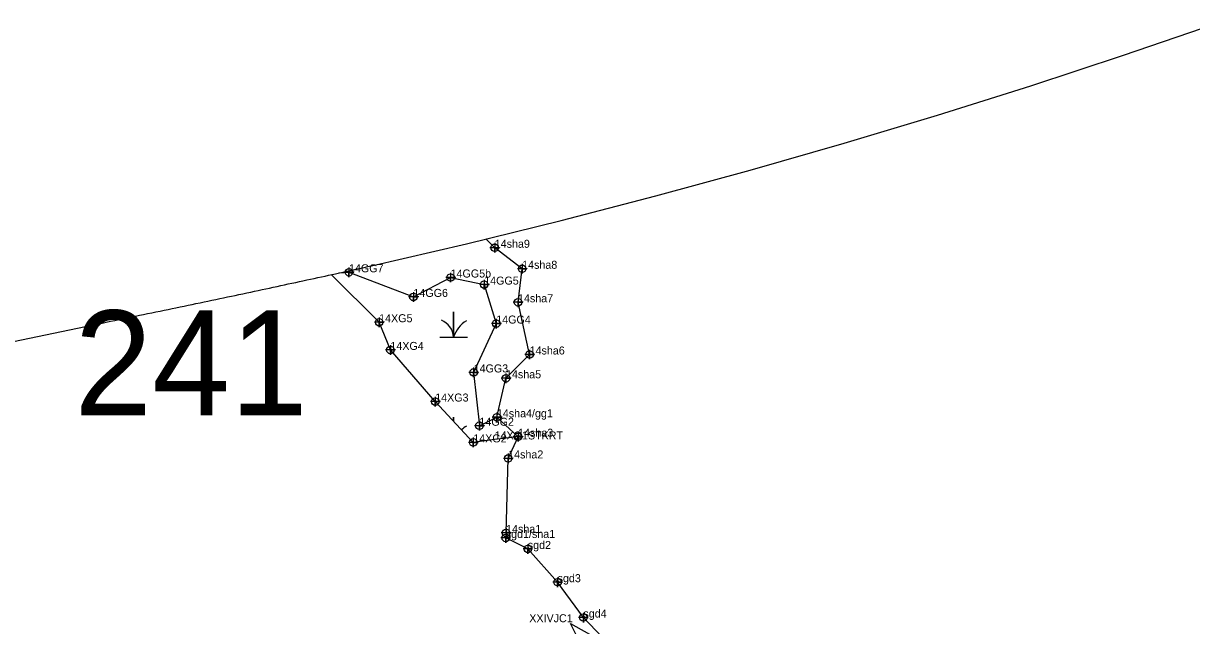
# Model space of a CAD drawing. Extents: x 2071991 to 2268989, y 436479 to 469629.
# Drawn here: x 2262836 to 2263565, y 442642 to 443018 of the extents above; entities that cross this region are included whole.
import ezdxf

# ---------------------------------------------------------------- set-up
doc = ezdxf.new("R2010")
doc.units = 0
for name, color, linetype in [('approx_PSA', 7, 'Continuous'), ('Default', 7, 'Continuous'), ('Exist Environmental Wetland Boundary', 7, 'Continuous'), ('Exist Environmental Wetland Boundary Cogo Comment', 7, 'Continuous'), ('Exist Environmental Wetland Boundary Cogo Point CELL', 7, 'Continuous'), ('Exist Hydro Jurisdictional Stream or Body of Water NEU Mitigable', 7, 'Continuous'), ('Exist Hydro Jurisdictional Stream or Body of Water NEU Mitigable Cogo Comment', 7, 'Continuous'), ('Exist Hydro Jurisdictional Stream or Body of Water NEU Mitigable Cogo Point CELL', 7, 'Continuous'), ('Exist Hydro Swamp or Marsh', 7, 'Continuous')]:
    doc.layers.add(name, color=color, linetype=linetype)

msp = doc.modelspace()

# ---------------------------------------------------------------- linework, layer by layer
at = {"layer": 'approx_PSA'}
for p, q in [((2263522.98, 442997.73), (2263580.7, 443017.56)), ((2263465, 442978.66), (2263522.98, 442997.73)), ((2263406.78, 442960.33), (2263465, 442978.66)), ((2263348.33, 442942.76), (2263406.78, 442960.33)), ((2263289.66, 442925.94), (2263348.33, 442942.76)), ((2263230.78, 442909.88), (2263289.66, 442925.94)), ((2263171.7, 442894.58), (2263230.78, 442909.88)), ((2263112.42, 442880.04), (2263171.7, 442894.58)), ((2263053.23, 442866.33), (2263112.42, 442880.04)), ((2263030.75, 442861.33), (2263033.17, 442861.87)), ((2263033.17, 442861.87), (2263035.46, 442862.37)), ((2263035.46, 442862.37), (2263037.57, 442862.84)), ((2263037.57, 442862.84), (2263039.82, 442863.33)), ((2263039.82, 442863.33), (2263041.89, 442863.79)), ((2263041.89, 442863.79), (2263044.17, 442864.3)), ((2263044.17, 442864.3), (2263046.46, 442864.81)), ((2263046.46, 442864.81), (2263048.53, 442865.28)), ((2263048.53, 442865.28), (2263050.77, 442865.78)), ((2263050.77, 442865.78), (2263052.96, 442866.27)), ((2263052.96, 442866.27), (2263053.23, 442866.33)), ((2262998.77, 442854.38), (2263001.2, 442854.9)), ((2263001.2, 442854.9), (2263003.49, 442855.39)), ((2263003.49, 442855.39), (2263005.96, 442855.93)), ((2263005.96, 442855.93), (2263008.24, 442856.42)), ((2263008.24, 442856.42), (2263010.32, 442856.87)), ((2263010.32, 442856.87), (2263012.74, 442857.4)), ((2263012.74, 442857.4), (2263015.03, 442857.89)), ((2263015.03, 442857.89), (2263017.32, 442858.39)), ((2263017.32, 442858.39), (2263019.57, 442858.88)), ((2263019.57, 442858.88), (2263021.82, 442859.37)), ((2263021.82, 442859.37), (2263024.14, 442859.88)), ((2263024.14, 442859.88), (2263026.39, 442860.37)), ((2263026.39, 442860.37), (2263028.64, 442860.87)), ((2263028.64, 442860.87), (2263030.75, 442861.33)), ((2262963.17, 442846.81), (2262965.63, 442847.33)), ((2262965.63, 442847.33), (2262967.92, 442847.81)), ((2262967.92, 442847.81), (2262970.35, 442848.33)), ((2262970.35, 442848.33), (2262972.82, 442848.85)), ((2262972.82, 442848.85), (2262975.29, 442849.37)), ((2262975.29, 442849.37), (2262977.75, 442849.89)), ((2262977.75, 442849.89), (2262980.04, 442850.38)), ((2262980.04, 442850.38), (2262982.29, 442850.86)), ((2262982.29, 442850.86), (2262984.76, 442851.38)), ((2262984.76, 442851.38), (2262987.23, 442851.91)), ((2262987.23, 442851.91), (2262989.48, 442852.39)), ((2262989.48, 442852.39), (2262991.77, 442852.88)), ((2262991.77, 442852.88), (2262994.2, 442853.4)), ((2262994.2, 442853.4), (2262996.49, 442853.89)), ((2262996.49, 442853.89), (2262998.77, 442854.38)), ((2262928.58, 442839.58), (2262931.01, 442840.08)), ((2262931.01, 442840.08), (2262933.62, 442840.63)), ((2262933.62, 442840.63), (2262936.13, 442841.15)), ((2262936.13, 442841.15), (2262938.6, 442841.66)), ((2262938.6, 442841.66), (2262941.03, 442842.17)), ((2262941.03, 442842.17), (2262943.49, 442842.69)), ((2262943.49, 442842.69), (2262946.14, 442843.24)), ((2262946.14, 442843.24), (2262948.61, 442843.75)), ((2262948.61, 442843.75), (2262950.9, 442844.23)), ((2262950.9, 442844.23), (2262953.33, 442844.74)), ((2262953.33, 442844.74), (2262955.98, 442845.3)), ((2262955.98, 442845.3), (2262958.44, 442845.82)), ((2262958.44, 442845.82), (2262960.73, 442846.3)), ((2262960.73, 442846.3), (2262963.17, 442846.81)), ((2262892.81, 442832.16), (2262895.24, 442832.67)), ((2262895.24, 442832.67), (2262897.89, 442833.21)), ((2262897.89, 442833.21), (2262900.57, 442833.77)), ((2262900.57, 442833.77), (2262903.18, 442834.31)), ((2262903.18, 442834.31), (2262905.83, 442834.86)), ((2262905.83, 442834.86), (2262908.3, 442835.37)), ((2262908.3, 442835.37), (2262910.77, 442835.88)), ((2262910.77, 442835.88), (2262913.24, 442836.39)), ((2262913.24, 442836.39), (2262915.88, 442836.94)), ((2262915.88, 442836.94), (2262918.53, 442837.49)), ((2262918.53, 442837.49), (2262921.14, 442838.03)), ((2262921.14, 442838.03), (2262923.61, 442838.54)), ((2262923.61, 442838.54), (2262926.07, 442839.06)), ((2262926.07, 442839.06), (2262928.58, 442839.58)), ((2261971.8, 442641.95), (2262874.46, 442828.37)), ((2262874.46, 442828.37), (2262877.1, 442828.92)), ((2262877.1, 442828.92), (2262879.58, 442829.43)), ((2262879.58, 442829.43), (2262882.4, 442830.01)), ((2262882.4, 442830.01), (2262885.01, 442830.55)), ((2262885.01, 442830.55), (2262887.48, 442831.06)), ((2262887.48, 442831.06), (2262890.16, 442831.61)), ((2262890.16, 442831.61), (2262892.81, 442832.16))]:
    msp.add_line(p, q, dxfattribs=at)
at = {"layer": 'Exist Environmental Wetland Boundary'}
for points in [[(2263032.85, 442861.79), (2263039.09, 442862.2), (2263079.34, 442846.83), (2263102.57, 442858.94), (2263123.56, 442854.51), (2263131.08, 442830.2), (2263116.97, 442799.7), (2263120.56, 442766.42), (2263131.48, 442771.69)], [(2263144.73, 442759.55), (2263130.06, 442757.87), (2263116.73, 442756.04), (2263092.96, 442781.52), (2263064.96, 442813.74), (2263057.94, 442831.02), (2263028.01, 442860.73)], [(2263186.56, 442624.69), (2263177.46, 442642.93), (2263219.65, 442619.26)]]:
    msp.add_lwpolyline(points, dxfattribs=at)
at = {"layer": 'Exist Environmental Wetland Boundary Cogo Point CELL'}
for points in [[(2263039.09, 442865.2), (2263039.09, 442859.2), (2263039.09, 442862.2), (2263042.09, 442862.2), (2263036.09, 442862.2)], [(2263102.57, 442861.94), (2263102.57, 442855.94), (2263102.57, 442858.94), (2263105.57, 442858.94), (2263099.57, 442858.94)], [(2263123.56, 442857.51), (2263123.56, 442851.51), (2263123.56, 442854.51), (2263126.56, 442854.51), (2263120.56, 442854.51)], [(2263079.34, 442849.83), (2263079.34, 442843.83), (2263079.34, 442846.83), (2263082.34, 442846.83), (2263076.34, 442846.83)], [(2263057.94, 442834.02), (2263057.94, 442828.02), (2263057.94, 442831.02), (2263060.94, 442831.02), (2263054.94, 442831.02)], [(2263131.08, 442833.2), (2263131.08, 442827.2), (2263131.08, 442830.2), (2263134.08, 442830.2), (2263128.08, 442830.2)], [(2263064.96, 442816.74), (2263064.96, 442810.74), (2263064.96, 442813.74), (2263067.96, 442813.74), (2263061.96, 442813.74)], [(2263116.97, 442802.7), (2263116.97, 442796.7), (2263116.97, 442799.7), (2263119.97, 442799.7), (2263113.97, 442799.7)], [(2263092.96, 442784.52), (2263092.96, 442778.52), (2263092.96, 442781.52), (2263095.96, 442781.52), (2263089.96, 442781.52)], [(2263131.48, 442774.69), (2263131.48, 442768.69), (2263131.48, 442771.69), (2263134.48, 442771.69), (2263128.48, 442771.69)], [(2263120.56, 442769.42), (2263120.56, 442763.42), (2263120.56, 442766.42), (2263123.56, 442766.42), (2263117.56, 442766.42)], [(2263144.73, 442762.55), (2263144.73, 442756.55), (2263144.73, 442759.55), (2263147.73, 442759.55), (2263141.73, 442759.55)], [(2263116.73, 442759.04), (2263116.73, 442753.04), (2263116.73, 442756.04), (2263119.73, 442756.04), (2263113.73, 442756.04)]]:
    msp.add_lwpolyline(points, dxfattribs=at)
for centre in [(2263039.09, 442862.2), (2263102.57, 442858.94), (2263123.56, 442854.51), (2263079.34, 442846.83), (2263057.94, 442831.02), (2263131.08, 442830.2), (2263064.96, 442813.74), (2263116.97, 442799.7), (2263092.96, 442781.52), (2263120.56, 442766.42), (2263131.48, 442771.69), (2263144.73, 442759.55), (2263116.73, 442756.04)]:
    msp.add_circle(centre, 2.34, dxfattribs=at)
at = {"layer": 'Exist Hydro Jurisdictional Stream or Body of Water NEU Mitigable'}
for points in [[(2263137.23, 442699.52), (2263138.53, 442746.02), (2263144.73, 442759.55), (2263131.48, 442771.69), (2263137.17, 442796.03), (2263151.93, 442810.9), (2263144.68, 442843.47), (2263147.26, 442864.39), (2263130.15, 442877.5), (2263124.49, 442883)], [(2263201.1, 442630.39), (2263185.52, 442646.71), (2263169.42, 442668.77), (2263150.8, 442689.51), (2263137.03, 442696.39)]]:
    msp.add_lwpolyline(points, dxfattribs=at)
at = {"layer": 'Exist Hydro Jurisdictional Stream or Body of Water NEU Mitigable Cogo Point CELL'}
for points in [[(2263130.15, 442880.5), (2263130.15, 442874.5), (2263130.15, 442877.5), (2263133.15, 442877.5), (2263127.15, 442877.5)], [(2263147.26, 442867.39), (2263147.26, 442861.39), (2263147.26, 442864.39), (2263150.26, 442864.39), (2263144.26, 442864.39)], [(2263144.68, 442846.47), (2263144.68, 442840.47), (2263144.68, 442843.47), (2263147.68, 442843.47), (2263141.68, 442843.47)], [(2263151.93, 442813.9), (2263151.93, 442807.9), (2263151.93, 442810.9), (2263154.93, 442810.9), (2263148.93, 442810.9)], [(2263137.17, 442799.03), (2263137.17, 442793.03), (2263137.17, 442796.03), (2263140.17, 442796.03), (2263134.17, 442796.03)], [(2263144.73, 442762.55), (2263144.73, 442756.55), (2263144.73, 442759.55), (2263147.73, 442759.55), (2263141.73, 442759.55)], [(2263138.53, 442749.02), (2263138.53, 442743.02), (2263138.53, 442746.02), (2263141.53, 442746.02), (2263135.53, 442746.02)], [(2263137.23, 442702.52), (2263137.23, 442696.52), (2263137.23, 442699.52), (2263140.23, 442699.52), (2263134.23, 442699.52)], [(2263137.03, 442699.39), (2263137.03, 442693.39), (2263137.03, 442696.39), (2263140.03, 442696.39), (2263134.03, 442696.39)], [(2263150.8, 442692.51), (2263150.8, 442686.51), (2263150.8, 442689.51), (2263153.8, 442689.51), (2263147.8, 442689.51)], [(2263169.42, 442671.77), (2263169.42, 442665.77), (2263169.42, 442668.77), (2263172.42, 442668.77), (2263166.42, 442668.77)], [(2263185.52, 442649.71), (2263185.52, 442643.71), (2263185.52, 442646.71), (2263188.52, 442646.71), (2263182.52, 442646.71)]]:
    msp.add_lwpolyline(points, dxfattribs=at)
for centre in [(2263130.15, 442877.5), (2263147.26, 442864.39), (2263144.68, 442843.47), (2263151.93, 442810.9), (2263137.17, 442796.03), (2263144.73, 442759.55), (2263138.53, 442746.02), (2263137.23, 442699.52), (2263137.03, 442696.39), (2263150.8, 442689.51), (2263169.42, 442668.77), (2263185.52, 442646.71)]:
    msp.add_circle(centre, 2.34, dxfattribs=at)
at = {"layer": 'Exist Hydro Swamp or Marsh'}
for points in [[(2263095.85, 442821.77), (2263104.45, 442821.77), (2263104.45, 442837.55), (2263104.45, 442821.77), (2263113.05, 442821.77)], [(2263104.45, 442769.21), (2263104.45, 442771.77), (2263104.45, 442769.21)]]:
    msp.add_lwpolyline(points, dxfattribs=at)
for centre, radius, start, end in [((2263092.18, 442820.88), 12.3, 4.14034, 67.53497), ((2263122.69, 442815.7), 19.22, 122.12745, 161.62219), ((2263122.69, 442749.92), 19.22, 122.12745, 133.56574)]:
    msp.add_arc(centre, radius, start, end, dxfattribs=at)

# ---------------------------------------------------------------- texts
at = {"layer": 'Default'}
msp.add_text('241', height=65.34, dxfattribs=at).set_placement((2262867.57, 442773.02))
at = {"layer": 'Exist Environmental Wetland Boundary Cogo Comment'}
for s, p in [('14GG7', (2263039.09, 442862.2)), ('14GG5b', (2263102.57, 442858.94)), ('14GG5', (2263123.56, 442854.51)), ('14GG6', (2263079.34, 442846.83)), ('14XG5', (2263057.94, 442831.02)), ('14GG4', (2263131.08, 442830.2)), ('14XG4', (2263064.96, 442813.74)), ('14GG3', (2263116.97, 442799.7)), ('14XG3', (2263092.96, 442781.52)), ('14GG2', (2263120.56, 442766.42)), ('14XG2', (2263116.73, 442756.04)), ('14XG1STKRT', (2263130.06, 442757.87)), ('XXIVJC1 ', (2263151.72, 442643.76))]:
    msp.add_text(s, height=5, dxfattribs=at).set_placement(p)
at = {"layer": 'Exist Hydro Jurisdictional Stream or Body of Water NEU Mitigable Cogo Comment'}
for s, p in [('14sha9', (2263130.15, 442877.5)), ('14sha8', (2263147.26, 442864.39)), ('14sha7', (2263144.68, 442843.47)), ('14sha6', (2263151.93, 442810.9)), ('14sha5', (2263137.17, 442796.03)), ('14sha4/gg1', (2263131.48, 442771.69)), ('14sha3', (2263144.73, 442759.55)), ('14sha2', (2263138.53, 442746.02)), ('sgd1/sha1', (2263137.03, 442696.39)), ('14sha1', (2263137.23, 442699.52)), ('sgd2', (2263150.8, 442689.51)), ('sgd3', (2263169.42, 442668.77)), ('sgd4', (2263185.52, 442646.71))]:
    msp.add_text(s, height=5, dxfattribs=at).set_placement(p)

doc.saveas('drawing.dxf')
